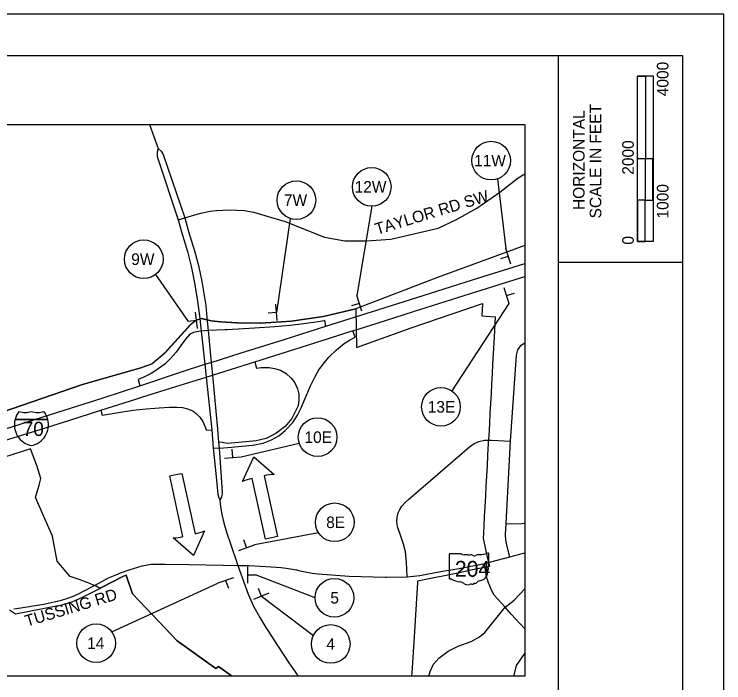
# Model space of a CAD drawing. Extents: x 1880545 to 1948545, y 79309 to 723051.
# Drawn here: x 1931372 to 1948545, y 706870 to 723051 of the extents above; entities that cross this region are included whole.
import ezdxf

# ---------------------------------------------------------------- set-up
doc = ezdxf.new("R2010")
doc.units = 0
for name, color, linetype in [('GM_X_Corporation', 7, 'Continuous'), ('GM_X_County_Road', 7, 'Continuous'), ('GM_X_Interchange_Ramps', 7, 'Continuous'), ('GM_X_Interstate_Route', 7, 'Continuous'), ('GM_X_Interstate_Shield', 7, 'Continuous'), ('GM_X_State_Route', 7, 'Continuous'), ('GM_X_State_Shield', 7, 'Continuous'), ('GM_X_Township_Road', 7, 'Continuous'), ('SH_Border', 7, 'Continuous'), ('SH_Cut_Line', 7, 'Continuous'), ('SH_Data', 7, 'Continuous'), ('SH_Text', 7, 'Continuous')]:
    doc.layers.add(name, color=color, linetype=linetype)

msp = doc.modelspace()

# ---------------------------------------------------------------- linework, layer by layer
at = {"layer": 'GM_X_Corporation'}
for points in [[(1943726, 717450), (1942669, 717062), (1941614, 716676), (1939637, 715922), (1938859, 715737), (1938079, 715624), (1937344, 715571), (1936771, 715583), (1936370, 715605), (1936142, 715633), (1935914, 715683), (1935786, 715649), (1935647, 715544), (1935024, 714853), (1934712, 714592), (1934436, 714491), (1933024, 714093), (1931080, 713417), (1930727, 713289), (1930736, 713260), (1929234, 712782), (1929171, 712762)], [(1931080, 713417), (1933024, 714093), (1934436, 714491), (1934705, 714592), (1935017, 714853), (1935640, 715544), (1935779, 715649), (1935907, 715683), (1936136, 715633), (1936364, 715605), (1936764, 715583), (1937338, 715571), (1938073, 715624), (1938852, 715737), (1939637, 715922), (1939659, 714983), (1940978, 715462), (1942709, 716047), (1942692, 715748), (1943013, 715726), (1942986, 715236), (1942964, 714829), (1942950, 714585), (1942937, 714345), (1942924, 714106), (1942911, 713866), (1942898, 713626), (1942885, 713386), (1942872, 713147), (1942855, 712847), (1942845, 712668), (1942829, 712368), (1942816, 712122), (1942789, 711631), (1942775, 711385), (1942762, 711140), (1942748, 710894), (1942747, 710876), (1942735, 710649), (1942719, 710361), (1942808, 709947), (1942878, 709686), (1942636, 709635), (1942422, 709592), (1942147, 709535), (1941135, 709330), (1941134, 709311), (1941133, 709298), (1941041, 707857), (1941026, 707617), (1941001, 707226), (1940989, 707032)], [(1936637, 707032), (1936637, 707033), (1936634, 707035), (1936316, 707268), (1936249, 707213), (1935320, 707884), (1934709, 708526), (1934234, 709025), (1934082, 709478), (1934003, 709441), (1933469, 709167), (1933445, 709155), (1933359, 709205), (1933310, 709227), (1933206, 709274), (1932966, 709360), (1932723, 709446), (1932630, 709557), (1932413, 709814), (1932300, 710420), (1931888, 711352), (1931973, 711651), (1932020, 711815), (1931917, 712126), (1931765, 712529), (1930907, 712258)], [(1931258, 708635), (1931401, 708536), (1932400, 708730), (1932533, 708759), (1932665, 708796), (1932794, 708840), (1932920, 708891), (1933044, 708949), (1933445, 709155), (1933469, 709167), (1934003, 709441), (1934082, 709478), (1934234, 709025), (1934709, 708526), (1935033, 708185), (1935320, 707884), (1936249, 707213), (1936316, 707268), (1936634, 707035), (1936637, 707033), (1936637, 707032)]]:
    msp.add_lwpolyline(points, dxfattribs=at)
at = {"layer": 'GM_X_County_Road'}
msp.add_lwpolyline([(1935338, 718076), (1935499, 718124), (1935880, 718238), (1936114, 718285), (1936271, 718299), (1936572, 718319), (1936943, 718299), (1937164, 718262), (1937928, 718031), (1938879, 717651), (1939375, 717570), (1939895, 717570), (1940490, 717606), (1941630, 717871), (1942075, 718083), (1942568, 718356), (1943121, 718741), (1943571, 719087), (1943726, 719189)], dxfattribs=at)
at = {"layer": 'GM_X_Interchange_Ramps'}
for p, q in [((1936064, 715393), (1935900, 715382)), ((1939623, 715231), (1939570, 715389))]:
    msp.add_line(p, q, dxfattribs=at)
for points in [[(1938877, 715632), (1938731, 715608), (1938380, 715561), (1938050, 715515), (1937683, 715485), (1937187, 715452), (1936527, 715413)], [(1938915, 715498), (1938893, 715635), (1938877, 715632)], [(1936527, 715413), (1936480, 715410), (1936064, 715393)], [(1935900, 715382), (1935834, 715369), (1935712, 715345), (1935625, 715305), (1935521, 715190), (1935405, 715031), (1935289, 714869), (1935146, 714707), (1935018, 714585), (1934860, 714468)], [(1936187, 712554), (1936332, 712548), (1936544, 712562), (1937139, 712619), (1937394, 712669), (1937600, 712749), (1937777, 712847), (1937932, 712977), (1938119, 713167), (1938226, 713344), (1938318, 713522), (1938544, 714055), (1938646, 714265), (1938747, 714441), (1938883, 714622), (1938988, 714754), (1939168, 714927), (1939358, 715079), (1939490, 715159), (1939623, 715231)], [(1937196, 714638), (1937232, 714482), (1937346, 714499), (1937540, 714499), (1937672, 714480), (1937816, 714440), (1937953, 714357), (1938074, 714242), (1938162, 714126), (1938226, 713987), (1938262, 713854), (1938262, 713721), (1938242, 713569)], [(1934860, 714468), (1934846, 714457), (1934690, 714357), (1934506, 714265), (1934369, 714208), (1934411, 714060)], [(1933471, 713469), (1933502, 713350), (1933846, 713406), (1934244, 713464), (1934569, 713500), (1934879, 713527), (1935132, 713540), (1935307, 713543), (1935447, 713532), (1935563, 713502), (1935693, 713452), (1935777, 713386), (1935866, 713301), (1935937, 713193), (1936030, 712987), (1936153, 712993)], [(1938242, 713569), (1938182, 713444), (1938092, 713265), (1937927, 713071), (1937707, 712903), (1937471, 712785), (1937225, 712722), (1936979, 712698), (1936715, 712677), (1936536, 712664), (1936409, 712686), (1936319, 712696)]]:
    msp.add_lwpolyline(points, dxfattribs=at)
at = {"layer": 'GM_X_Interstate_Route'}
for points in [[(1938915, 715498), (1940326, 715943), (1941449, 716303), (1942461, 716620), (1943726, 717017)], [(1939555, 715384), (1939570, 715389), (1940155, 715575), (1941033, 715853), (1942415, 716291), (1943726, 716704)], [(1937206, 714962), (1937902, 715181), (1938915, 715498)], [(1937346, 714686), (1937988, 714890), (1939001, 715207), (1939555, 715384)], [(1934411, 714060), (1935445, 714405), (1935984, 714578), (1936135, 714625), (1936866, 714854), (1937206, 714962)], [(1934318, 713735), (1934488, 713788), (1935282, 714037), (1936014, 714266), (1936170, 714315), (1937196, 714638), (1937346, 714686)], [(1929171, 712405), (1929396, 712464), (1930250, 712732), (1930977, 712960), (1931513, 713128), (1932405, 713411), (1933524, 713766), (1934411, 714060)], [(1929594, 712248), (1930547, 712544), (1931062, 712707), (1931244, 712764), (1931895, 712967), (1932698, 713221), (1933471, 713469), (1934318, 713735)]]:
    msp.add_lwpolyline(points, dxfattribs=at)
at = {"layer": 'GM_X_Interstate_Shield'}
for p, q in [((1931393, 713243), (1932187, 713243)), ((1932187, 713243), (1931393, 713243)), ((1932187, 713243), (1931393, 713243))]:
    msp.add_line(p, q, dxfattribs=at)
for centre, start, end in [((1931893, 713116), 141.669, 165.8066), ((1931639, 713929), 253.0091, 286.9909), ((1931940, 713929), 253.0091, 286.9909), ((1931687, 713116), 14.1934, 38.331), ((1931893, 713116), 165.8066, 258.463), ((1931687, 713116), 281.537, 14.1934)]:
    msp.add_arc(centre, 516, start, end, dxfattribs=at)
at = {"layer": 'GM_X_State_Route'}
for p, q in [((1934643, 720381), (1934854, 719799)), ((1935861, 715683), (1935900, 715382))]:
    msp.add_line(p, q, dxfattribs=at)
for points in [[(1934854, 719799), (1934835, 719713), (1934835, 719611), (1935338, 718076)], [(1934854, 719799), (1934932, 719738), (1934976, 719653), (1935499, 718124), (1935593, 717789), (1935738, 717328), (1935836, 716968), (1935916, 716581), (1936012, 715999), (1936037, 715712), (1936064, 715393)], [(1935338, 718076), (1935425, 717784), (1935567, 717310), (1935657, 716954), (1935731, 716592), (1935799, 716166), (1935861, 715683)], [(1935900, 715382), (1935984, 714578), (1936014, 714266), (1936153, 712993), (1936187, 712554)], [(1936064, 715393), (1936135, 714625), (1936170, 714315), (1936296, 713005), (1936319, 712696), (1936332, 712548), (1936380, 711852), (1936405, 711456), (1936391, 711362), (1936348, 711294)], [(1936187, 712554), (1936262, 711856), (1936298, 711436), (1936323, 711350), (1936348, 711294)], [(1936348, 711294), (1936366, 711128), (1936400, 710942), (1936429, 710808), (1936468, 710656), (1936525, 710470), (1936599, 710255), (1936781, 709712)], [(1942751, 709758), (1943366, 709919), (1943726, 710014)], [(1940385, 709428), (1940885, 709432), (1941187, 709465), (1941736, 709571), (1942141, 709635), (1942751, 709758)], [(1936781, 709712), (1937059, 709712), (1937587, 709680), (1937833, 709663), (1938008, 709639), (1938207, 709600), (1938255, 709589)], [(1936781, 709712), (1937032, 709017), (1937166, 708722), (1937313, 708447), (1937464, 708210), (1937497, 708157)], [(1938255, 709589), (1938416, 709554), (1938583, 709526), (1938729, 709508), (1939476, 709454), (1940351, 709428), (1940385, 709428)], [(1937497, 708157), (1937758, 707748), (1938022, 707350), (1938248, 707032)]]:
    msp.add_lwpolyline(points, dxfattribs=at)
at = {"layer": 'GM_X_State_Shield'}
for p, q in [((1941901, 709978), (1941901, 709396)), ((1942190, 709988), (1941910, 709988)), ((1942858, 709698), (1942858, 710002)), ((1942858, 709698), (1942858, 709698))]:
    msp.add_line(p, q, dxfattribs=at)
for centre, major_axis, start_param, end_param in [((1941912, 709979), (11.1, 0), 1.712693, 3.28349), ((1942257, 710055), (108, 0), 4.042523, 4.731795), ((1942293, 709661), (386, 0), 1.404758, 1.657858), ((1942380, 709982), (31, 0), 3.836095, 5.185415), ((1942426, 709915), (64.5, 0), 0.950623, 2.079405), ((1942509, 710007), (77.6, 0), 4.081561, 5.145723), ((1942646, 709810), (204, 0), 1.699011, 2.107814), ((1942517, 710780), (1015, 0), 4.814394, 5.042369), ((1942847, 710003), (10.7, 0), 6.141152, 7.989035), ((1942574, 709532), (254, 0), 5.101752, 6.440018), ((1942896, 709571), (72, 0), 2.387724, 3.262537), ((1942855, 709676), (16.5, 0), 1.883978, 3.671073), ((1942750, 709637), (99, 0), 5.934695, 6.695948), ((1942846, 709697), (11.4, 0), 5.05454, 6.418171), ((1941912, 709395), (11.2, 0), 3.00124, 4.508301), ((1941913, 709455), (85.4, 0), 4.665946, 4.897461), ((1941931, 709363), (30.8, 0), 0.519207, 1.627899), ((1942320, 709885), (733, 0), 4.195997, 4.488961), ((1942101, 709135), (229, 0), 0.823519, 1.323587), ((1942349, 709360), (146, 0), 4.026481, 4.996735), ((1942433, 709159), (120, 0), 1.495662, 1.94098), ((1942444, 709317), (77.5, 0), 4.691044, 5.507374), ((1942514, 709260), (21.8, 0), 1.147584, 2.315152), ((1942505, 709340), (82, 0), 4.937069, 5.64225), ((1942681, 709233), (139, 0), 1.647645, 2.488434)]:
    msp.add_ellipse(centre, major_axis=major_axis, ratio=0.8, start_param=start_param, end_param=end_param, dxfattribs=at)
at = {"layer": 'GM_X_Township_Road'}
msp.add_line((1943726, 708173), (1943401, 708534), dxfattribs=at)
for points in [[(1943366, 709919), (1943301, 710165), (1943270, 710319), (1943265, 710458), (1943277, 710722), (1943381, 712719), (1943531, 714797), (1943561, 714926), (1943642, 715038), (1943726, 715095)], [(1940885, 709432), (1940866, 709793), (1940843, 710037), (1940797, 710223), (1940719, 710444), (1940651, 710646), (1940636, 710775), (1940642, 710882), (1940667, 710985), (1940701, 711061), (1940756, 711145), (1940839, 711238), (1940922, 711317), (1941621, 711919), (1942389, 712578), (1942503, 712658), (1942616, 712707), (1942757, 712744), (1942846, 712744)], [(1942846, 712744), (1942920, 712744), (1943381, 712719)], [(1943277, 710722), (1943635, 710720), (1943726, 710738)], [(1933857, 709492), (1933944, 709529), (1934152, 709604), (1934469, 709697), (1934686, 709739), (1935026, 709739), (1935610, 709736), (1936428, 709717), (1936781, 709712)], [(1943401, 708534), (1943251, 708699), (1942988, 708994), (1942932, 709094), (1942853, 709293), (1942801, 709431), (1942751, 709758)], [(1933434, 709287), (1933656, 709407), (1933857, 709492)], [(1931367, 708657), (1931427, 708670), (1932088, 708773), (1932514, 708871), (1932670, 708915), (1932786, 708960), (1932911, 709016), (1933254, 709190), (1933434, 709287)], [(1941407, 707032), (1941440, 707147), (1941521, 707317), (1941646, 707463), (1941871, 707639), (1942114, 707756), (1942433, 707867), (1942632, 707979), (1942764, 708087), (1943251, 708699), (1943472, 708866), (1943726, 709148)], [(1943475, 707032), (1943473, 707055), (1943530, 707289), (1943726, 707580)]]:
    msp.add_lwpolyline(points, dxfattribs=at)
at = {"layer": 'SH_Border'}
for p, q in [((1944545, 680051), (1944545, 722051)), ((1944545, 717051), (1947545, 717051))]:
    msp.add_line(p, q, dxfattribs=at)
msp.add_lwpolyline([(1883545, 722051), (1947545, 722051), (1947545, 680051), (1883545, 680051)], close=True, dxfattribs=at)
at = {"layer": 'SH_Cut_Line'}
msp.add_lwpolyline([(1880545, 679051), (1948545, 679051), (1948545, 723051), (1880545, 723051)], close=True, dxfattribs=at)
at = {"layer": 'SH_Data'}
for p, q in [((1946458, 717551), (1946458, 721551)), ((1946833, 721551), (1946458, 721551)), ((1946458, 719551), (1946458, 721551)), ((1946458, 721551), (1946645, 721551)), ((1946645, 721551), (1946646, 721551)), ((1946646, 721551), (1946646, 719551)), ((1946833, 721551), (1946833, 717551)), ((1946646, 719551), (1946458, 719551)), ((1946831, 719551), (1946645, 719551)), ((1946645, 719551), (1946645, 718551)), ((1946831, 718551), (1946831, 719551)), ((1946645, 718551), (1946458, 718551)), ((1946458, 718551), (1946458, 717551)), ((1946645, 718551), (1946831, 718551)), ((1946645, 717551), (1946645, 718551)), ((1946833, 717551), (1946458, 717551)), ((1946458, 717551), (1946645, 717551))]:
    msp.add_line(p, q, dxfattribs=at)
at = {"layer": 'SH_Text'}
for p, q in [((1943069, 719066), (1943268, 717380)), ((1940024, 718404), (1939668, 716242)), ((1938048, 718108), (1937720, 715834)), ((1943388, 716998), (1943268, 717380)), ((1943328, 717189), (1943138, 717129)), ((1934795, 716754), (1935585, 715617)), ((1943225, 716433), (1943345, 716051)), ((1943285, 716242), (1943476, 716302)), ((1939788, 715861), (1939668, 716242)), ((1937737, 715635), (1937704, 716034)), ((1939728, 716051), (1939537, 715991)), ((1943345, 716051), (1941963, 713935)), ((1935809, 715444), (1935758, 715841)), ((1937720, 715834), (1937521, 715818)), ((1935783, 715642), (1935585, 715617)), ((1936863, 712336), (1938271, 712673)), ((1936664, 712322), (1936650, 712521)), ((1936464, 712308), (1936863, 712336)), ((1936898, 711745), (1937168, 712336)), ((1937168, 712336), (1937660, 711912)), ((1935136, 711875), (1935283, 711907)), ((1935457, 710410), (1935136, 711875)), ((1935283, 711907), (1935429, 711939)), ((1935429, 711939), (1935751, 710474)), ((1937450, 710350), (1937129, 711815)), ((1937422, 711880), (1937743, 710414)), ((1935981, 710544), (1935711, 709953)), ((1938739, 710497), (1937184, 710210)), ((1937743, 710414), (1937596, 710382)), ((1935711, 709953), (1935219, 710377)), ((1936996, 710142), (1936928, 710330)), ((1937596, 710382), (1937450, 710350)), ((1936808, 710074), (1937184, 710210)), ((1937015, 709680), (1937015, 709280)), ((1936676, 709414), (1936300, 709278)), ((1937015, 709480), (1937215, 709480)), ((1938654, 708927), (1937215, 709480)), ((1933736, 708101), (1936300, 709278)), ((1936488, 709346), (1936556, 709158)), ((1937174, 708896), (1937546, 709044)), ((1937360, 708970), (1937287, 709156)), ((1937360, 708970), (1938614, 708018))]:
    msp.add_line(p, q, dxfattribs=at)
msp.add_lwpolyline([(1929171, 720381), (1943726, 720381), (1943726, 707032), (1929171, 707032)], close=True, dxfattribs=at)
for centre in [(1942915, 719507), (1940024, 718872), (1938201, 718550), (1934507, 717122), (1941700, 713549), (1938716, 712815), (1939130, 710754), (1939122, 708927), (1933356, 707829), (1939032, 707809)]:
    msp.add_circle(centre, 468, dxfattribs=at)
for centre, start, end in [((1937450, 710350), 102.3712, 111.5879), ((1937743, 710414), 93.1546, 102.3712), ((1935429, 711939), 282.3712, 291.5879), ((1935136, 711875), 273.1546, 282.3712)]:
    msp.add_arc(centre, 1500, start, end, dxfattribs=at)

# ---------------------------------------------------------------- texts
at = {"layer": 'GM_X_Interstate_Shield'}
msp.add_text('70', height=343.8, dxfattribs=at).set_placement((1931579, 712843))
at = {"layer": 'GM_X_State_Shield'}
msp.add_text('204', height=382.9, dxfattribs=at).set_placement((1942036, 709437))
at = {"layer": 'SH_Data'}
for s, p in [('4000', (1947205, 721066)), ('SCALE IN FEET', (1945580, 718109)), ('HORIZONTAL', (1945175, 718312)), ('2000', (1946366, 719166)), ('1000', (1947205, 718107)), ('0', (1946366, 717474))]:
    msp.add_text(s, height=280, rotation=90, dxfattribs=at).set_placement(p)
at = {"layer": 'SH_Text'}
for s, p in [('11W', (1942502, 719367)), ('12W', (1939611, 718732)), ('7W', (1937900, 718410)), ('9W', (1934205, 716982)), ('13E', (1941380, 713409)), ('10E', (1938397, 712675)), ('8E', (1938922, 710614)), ('5', (1939023, 708787)), ('14', (1933139, 707689)), ('4', (1938927, 707669))]:
    msp.add_text(s, height=280, dxfattribs=at).set_placement(p)
for s, p in [('TAYLOR RD SW', (1940152, 717709)), ('TUSSING RD', (1931679, 708223))]:
    msp.add_text(s, height=280, rotation=16.8035, dxfattribs=at).set_placement(p)

doc.saveas('drawing.dxf')
